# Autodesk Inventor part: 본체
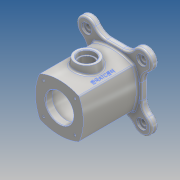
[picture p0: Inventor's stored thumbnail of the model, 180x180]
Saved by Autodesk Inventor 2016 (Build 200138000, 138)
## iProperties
Created: 2016-05
Part Number: 본체
Material: 알루미늄 6061
Document SubType Name: Modeling
Designer: Administrator
Density: 2.7 g/cm^3
Appearance: 알루미늄 - 평지
Mass: 1094 g
Surface Area: 856.534 cm^2
Volume: 405.187 cm^3
Author: Administrator
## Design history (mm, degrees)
sketch "스케치1"
  geometry: L1 (0, 0)-(-70.711, 70.711); L2 (0, 0)-(-118.695, 0); L3 (-70.711, 0)-(0, 70.711); L4 (7.604, 35.355)-(-78.314, 35.355); L5 (-35.355, -7.645)-(-35.355, 78.314); A1 r 86 centre (7.686, 35.355) between (-70.711, 70.711) and (-70.711, 0); A2 r 86 centre (-35.355, -7.686) between (0, 70.711) and (-70.711, 70.711); A3 r 85.162 centre (-77.476, 35.355) between (0, 0) and (0, 70.711); A4 r 85.162 centre (-35.355, 77.476) between (-70.711, 0) and (0, 0); 2 further points
  constraints: 12 point on circle, 10 end point, 4 centre point, 3 midpoint, 2 horizontal, 2 point on line, 1 perpendicular, 1 vertical
  dimensions: "d0" = 100 distance of L1.start L1.end; "d2" = 45 deg angle of L2 L1; "d3" = 100 distance of L3.start L3.end; "d4" = 50 distance from line of L1.start L3; "d103" = 86 distance of A1.centre L4.end; "d104" = 86 distance of A2.centre L5.end
extrude "돌출1" new body sketch "스케치1" distance "d9" = 98; taper "d10" = 0 deg
sketch "스케치4" dims "d38" = 140
  geometry: L1 (35.355, -35.355)-(-104.696, -35.355); L2 (35.355, -35.355)-(35.355, -161.613); L3 (35.355, -35.355)-(-81.211, -151.922); L4 (-13.645, -35.355)-(-13.645, -61.423); L5 (35.355, -84.355)-(21.194, -84.355); L6 (-13.645, -49.517)-(-13.645, -35.355); L7 (-13.645, -35.355)-(35.355, -35.355); L8 (35.355, -35.355)-(35.355, -84.355); A1 r 85.162 centre (77.476, -35.355) between (0, 0) and (0, -70.711) reference; A2 r 85.162 centre (35.355, -77.476) between (70.711, 0) and (0, 0) reference; A3 r 18 centre (-14.142, -84.853) between (-24.399, -70.061) and (0.65, -95.11); A4 r 25 centre (21.194, -109.355) between (21.194, -84.355) and (0.65, -95.11); A5 r 25 centre (-38.645, -49.517) between (-24.399, -70.061) and (-13.645, -49.517); 2 further points
  constraints: 16 end point, 8 point on circle, 3 centre point, 3 point on line, 2 collinear, 2 horizontal, 2 symmetric about line, 2 tangent, 2 vertical, 1 horizontal alignment, 1 vertical alignment, 4 other
  dimensions: "d39" = 45 deg angle of L2 L3; "d40" = 36 diameter of A3; "d42" = 49 distance between parallel lines of L4 L2; "d43" = 49 distance between parallel lines of L1 L5; "d44" = 50 diameter of A4
extrude "돌출2" join sketch "스케치4" distance "d45" = 12; taper "d46" = 0 deg
node "작업 평면1"
node "작업 평면2"
node "작업 평면3"
node "작업 평면5"
  node "작업 평면4"
sketch "스케치6"
  geometry: L1 (49.517, -98)-(-21.194, -98) reference; L2 (-21.194, -98)-(49.517, -98) reference; L3 (49.517, -98)-(49.517, 0) reference; L4 (-21.194, 0)-(49.517, 0) reference; L5 (-21.194, -98)-(-21.194, 0) reference; L6 (-21.194, -98)-(-21.194, 0) reference; L7 (-21.194, -49)-(49.517, -49); L8 (49.517, -98)-(49.517, 0) reference; C1 r 20 at (14.162, -49)
  constraints: 3 midpoint, 2 end point, 1 centre point
  dimensions: "d50" = 40 diameter of C1
extrude "돌출3" join sketch "스케치6" distance "d51" = 50; taper "d52" = 10 deg
sketch "스케치7"
  geometry: L1 (21.194, -98)-(-49.517, -98) reference; L2 (-14.162, -98)-(-14.162, 12); L3 (0, 12)-(-28.323, 12) reference; L4 (10.838, -98)-(10.838, -86); L5 (10.838, -86)-(20.838, -86); L6 (20.838, -86)-(20.838, 0); L7 (20.838, 0)-(10.838, 0); L8 (10.838, 0)-(10.838, 12); L9 (0, 12)-(20.544, 12) reference; L10 (10.838, -98)-(-14.162, -98); L11 (10.272, 12)-(-14.162, 12)
  constraints: 16 end point, 4 perpendicular, 3 midpoint, 2 collinear, 2 point on line, 1 vertical
  dimensions: "d53" = 70 diameter of L6 L2; "d54" = 86 distance between parallel lines of L7 L5; "d55" = 12 distance between parallel lines of L1 L5; "d56" = 50 diameter of L4 L2; "d57" = 50 diameter of L8 L2
revolve "회전1" sketch "스케치7" stored, may be unused: angle "d58" = 90 deg
sketch "스케치8"
  geometry: C1 r 20 at (0, 0) reference; 2 further points
  constraints: 1 coincident
hole "구멍1" sketch "스케치8" at (0, 0) diameter "d59" = 25; stored, may be unused: countersink angle "d63" = 90 deg, drill point angle "d65" = 0 deg; dims "d60" = 6, "d61" = 30, "d62" = 8, "d64" = 8
sketch "스케치10"
  geometry: A1 r 18 centre (84.853, -14.142) between (70.061, -24.399) and (95.11, 0.65) reference; A2 r 18 centre (84.853, 84.853) between (95.11, 70.061) and (70.061, 95.11) reference; A3 r 18 centre (-14.142, 84.853) between (0.65, 95.11) and (-24.399, 70.061) reference; A4 r 18 centre (-14.142, -14.142) between (-24.399, 0.65) and (0.65, -24.399) reference; 4 further points
  constraints: 4 coincident
hole "구멍2" sketch "스케치10" at (84.853, 84.853), (84.853, -14.142), (-14.142, -14.142), (-14.142, 84.853) diameter "d66" = 10; stored, may be unused: countersink angle "d70" = 90 deg, drill point angle "d72" = 0 deg; dims "d67" = 6, "d68" = 18, "d69" = 4, "d71" = 8
sketch "스케치11"
  geometry: L1 (-48.438, 119.148)-(147.325, -76.614); L2 (-55.014, -55.014)-(151.177, 151.177); L3 (10.355, 35.355)-(60.355, 35.355); A1 r 25 centre (35.355, 35.355) between (10.355, 35.355) and (60.355, 35.355) reference; A2 r 40 centre (35.355, 35.355) between (7.071, 63.64) and (7.071, 7.071); 2 further points
  constraints: 6 end point, 6 point on circle, 6 point on line, 1 centre point, 1 coincident, 1 horizontal, 1 midpoint
  dimensions: "d73" = 80 diameter of A2; "d74" = 45 deg angle of L1 L3; "d75" = 45 deg angle of L2 L3
hole "구멍3" sketch "스케치11" at (7.071, 63.64), (7.071, 7.071), (63.64, 7.071), (63.64, 63.64) diameter "d76" = 3.242; stored, may be unused: countersink angle "d80" = 90 deg, drill point angle "d82" = 118 deg; dims "d77" = 7, "d78" = 18, "d79" = 4, "d81" = 10
sketch "스케치12"
  geometry: L1 (75.355, -35.355)-(0.355, -35.355); L2 (35.355, -35.355)-(69.118, -69.118); C1 r 25 at (35.355, -35.355) reference; A1 r 40 centre (35.355, -35.355) between (75.355, -35.355) and (63.64, -63.64); 1 further point
  constraints: 4 end point, 2 point on circle, 2 point on line, 1 centre point, 1 coincident, 1 horizontal, 1 horizontal alignment, 1 other
  dimensions: "d83" = 80 diameter of A1; "d84" = 45 deg angle of L1 L2
hole "구멍4" sketch "스케치12" at (63.64, -63.64) diameter "d85" = 3.242; stored, may be unused: countersink angle "d89" = 90 deg, drill point angle "d91" = 118 deg; dims "d86" = 7, "d87" = 18, "d88" = 4, "d90" = 10
node "작업 평면6"
sketch "스케치13"
  geometry: L1 (49.162, -86)-(-20.838, -86) reference; L2 (49.162, 0)-(-20.838, 0) reference; C1 r 20 at (14.162, -49) reference; 3 further points
  constraints: 1 horizontal alignment, 2 other
  dimensions: "d96" = 29 distance of C1.centre point (43.162, -49)
feature "엠보싱1" sketch "스케치13" dims "d0" = 100, "d2" = 45 deg, "d3" = 100, "d4" = 50, "d38" = 140, "d39" = 45 deg, "d40" = 36, "d42" = 49, "d43" = 49, "d44" = 50, "d97" = 0.5, "d98" = 0, "d103" = 86, "d104" = 86
fillet "모깎기1" dims "d99" = 3
chamfer "모따기1" distance "d100" = 1; stored, may be unused: second distance "d101" = 2, angle "d102" = 45 deg
node "솔리드1"
mirror "대칭1"
mirror "대칭2"
pattern_circular "원형 패턴1" dims angle "d93" = 360 deg
node "투영된 루프2"
node "투영된 루프3"
other parameters: "d23" = 49, "d41" = 49, "d47" = 0, "d48" = 0, "d49" = 55
